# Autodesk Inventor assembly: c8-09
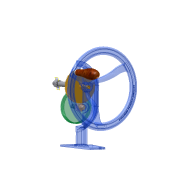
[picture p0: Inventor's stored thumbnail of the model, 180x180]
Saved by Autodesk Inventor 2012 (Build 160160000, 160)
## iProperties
Created: 2010-12
Part Number: c8-09
Document SubType Name: Assembly
Designer: Thom Tremblay
Author: Thom Tremblay
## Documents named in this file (12)
- C:\Users\VMuser\Desktop\Inventor 2012 Essentials\Assemblies\Chapter 8\c8-09.iam
- C:\Users\VMuser\Desktop\Inventor 2012 Essentials\Content Center Files\en-US\ISO 2795  F\ISO 2795 - 10 x 14 x 10F.ipt
- C:\Users\VMuser\Desktop\Inventor 2012 Essentials\Content Center Files\en-US\ISO 4032\ISO 4032 - M12ISO.ipt
- C:\Users\VMuser\Desktop\Inventor 2012 Essentials\Parts\Chapter 8\c8-04.ipt
- C:\Users\VMuser\Desktop\Inventor 2012 Essentials\Parts\Chapter 8\c8-05.ipt
- C:\Users\VMuser\Desktop\Inventor 2012 Essentials\Assemblies\Chapter 8\Design Accelerators\Shaft c8-01.iam
- C:\Users\VMuser\Desktop\Inventor 2012 Essentials\Assemblies\Chapter 8\Design Accelerators\Shaft c8-02.iam
- C:\Users\VMuser\Desktop\Inventor 2012 Essentials\Assemblies\Chapter 8\Design Accelerators\Cut Gear c08-01.iam
- C:\Users\VMuser\Desktop\Inventor 2012 Essentials\Assemblies\Chapter 8\Design Accelerators\Cut Gear c08-02.iam
- C:\Users\VMuser\Desktop\Inventor 2012 Essentials\Assemblies\Chapter 8\Design Accelerators\Spur Gear c98-01.iam
- C:\Users\VMuser\Desktop\Inventor 2012 Essentials\Parts\Chapter 8\c8-11.ipt
- C:\Users\VMuser\Desktop\Inventor 2012 Essentials\Assemblies\Chapter 8\Design Accelerators\Shaft c8-07.iam
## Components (12 placed, 9 different names)
1. c8-11:1 — Insert:1, Insert:2, Drive this Constraint
2. c8-04:1 — Insert:3, Mate:2, Mate:3, Angle:3
3. c8-05:1 — Insert:3
4. ISO 2795 (Flanged) 10 x 14 x 10:2 — Insert:2, Insert:6
5. ISO 2795 (Flanged) 10 x 14 x 10:3 — Insert:1, Insert:4
6. ISO 4032 M12:1 — Insert:7, Angle:1, Mate:4, Mate:5
7. Input Shaft [sub-assembly] — Insert:4, Mate:1, Mate:2, Mate:3, Angle:3
8. Output Shaft:2 [sub-assembly] — Insert:7, Mate:1, Flush:1, Angle:1, Rotation:1
9. Cut Gear:1 [sub-assembly]
10. Cut Gear:2 [sub-assembly]
11. Cut Gear:3 [sub-assembly] — Insert:5, Flush:1, Angle:2
12. New Shaft:1 [sub-assembly] — Insert:5, Insert:6, Angle:2, Rotation:1, Drive this Constraint
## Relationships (18: Insert 7, Mate 5, Angle 4, Flush 1, RelateRotation 1)
- Insert:1: c8-11:1 ↔ ISO 2795 (Flanged) 10 x 14 x 10:3
- Insert:2: c8-11:1 ↔ ISO 2795 (Flanged) 10 x 14 x 10:2
- Insert:3: c8-04:1 ↔ c8-05:1
- Insert:4: ISO 2795 (Flanged) 10 x 14 x 10:3 ↔ Input Shaft
- Insert:5: Cut Gear:3 ↔ New Shaft:1
- Insert:6: ISO 2795 (Flanged) 10 x 14 x 10:2 ↔ New Shaft:1
- Insert:7: ISO 4032 M12:1 ↔ Output Shaft:2
- Mate:1: Input Shaft ↔ Output Shaft:2
- Flush:1: Output Shaft:2 ↔ Cut Gear:3
- Angle:1: ISO 4032 M12:1 ↔ Output Shaft:2
- Angle:2: Cut Gear:3 ↔ New Shaft:1
- Mate:2: c8-04:1 ↔ Input Shaft
- Mate:3: c8-04:1 ↔ Input Shaft
- Angle:3: c8-04:1 ↔ Input Shaft
- Rotation:1 [RelateRotation]: Output Shaft:2 ↔ New Shaft:1
- Mate:4: ISO 4032 M12:1
- Mate:5: ISO 4032 M12:1
- Drive this Constraint [Angle]: c8-11:1 ↔ New Shaft:1
